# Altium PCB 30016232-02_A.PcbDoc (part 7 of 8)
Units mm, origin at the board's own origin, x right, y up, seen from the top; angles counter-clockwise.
Board outline 210 x 130 mm, 8 copper layers (1-TOP, 2-GND, 3-INTOP, 4-PWR, 5-PWR, 6-INBOT, 7-GND, 8-BOTTOM), stack 1.646 mm thick; 754 components, 649 nets, 2976 pads, 2161 vias.
Unrouted connection lines stored in the file: 22.
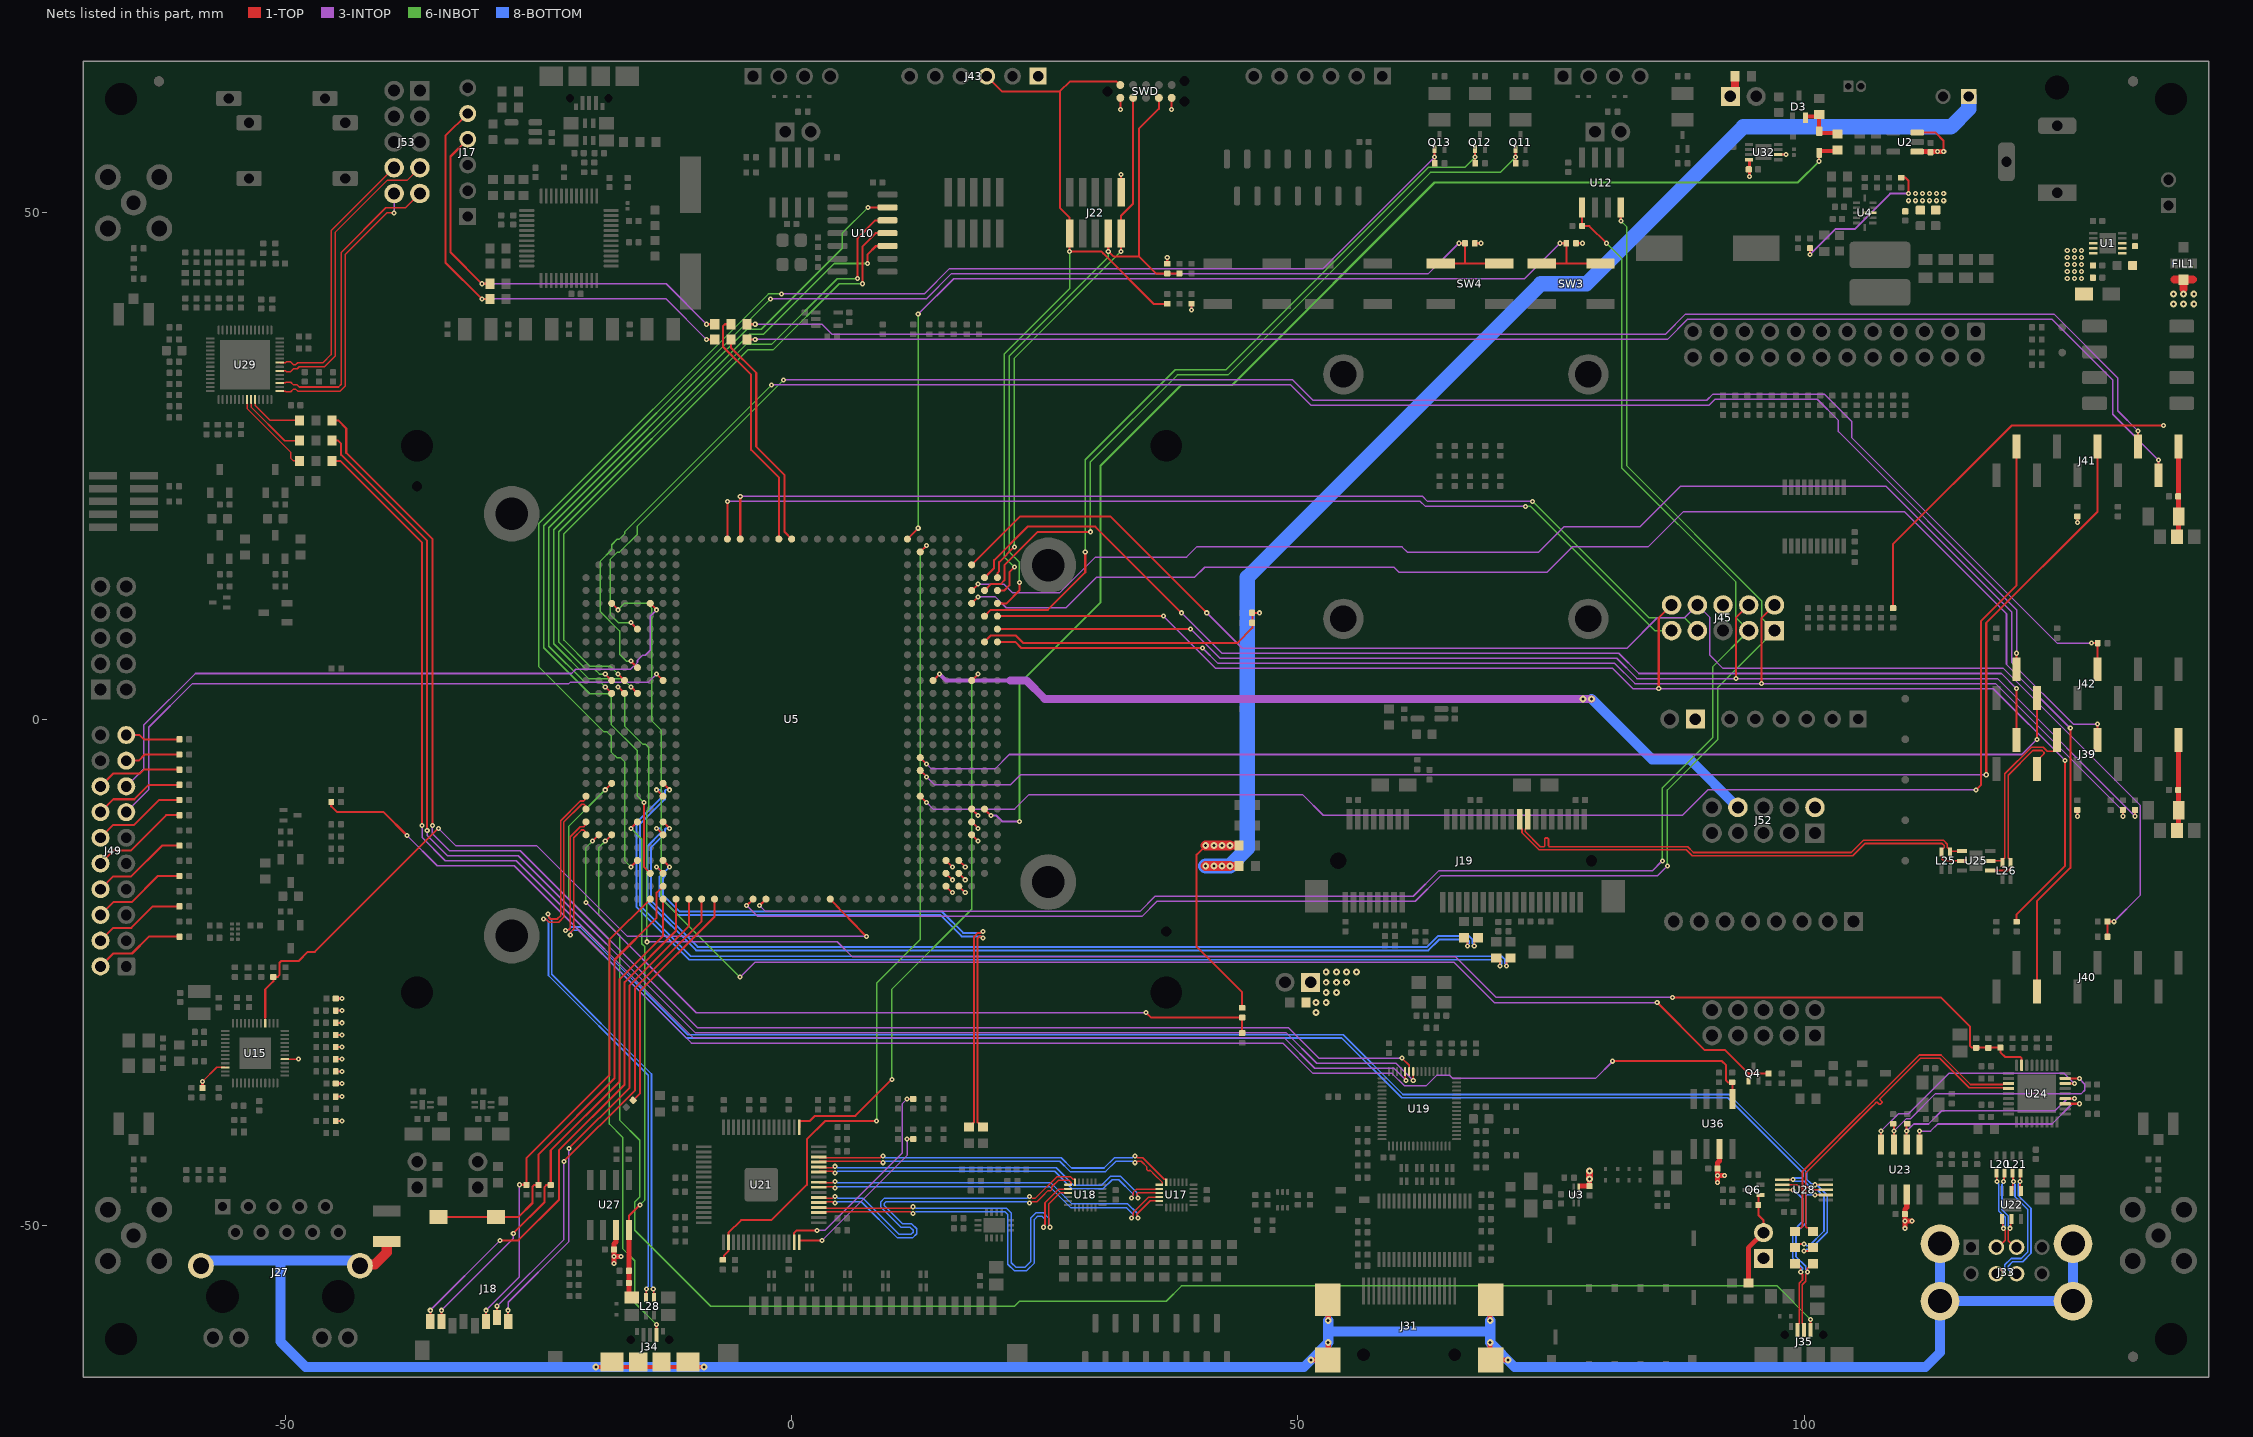
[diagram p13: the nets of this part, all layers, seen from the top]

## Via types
v1: diameter 0.5, hole 0.2, 1-TOP to 8-BOTTOM, 1742 vias
v2: diameter 0.5/0.5/0.5/0.5 (per signal layer), hole 0.2, 1-TOP to 8-BOTTOM, 237 vias
v3: diameter 0.68, hole 0.3, 1-TOP to 8-BOTTOM, 182 vias

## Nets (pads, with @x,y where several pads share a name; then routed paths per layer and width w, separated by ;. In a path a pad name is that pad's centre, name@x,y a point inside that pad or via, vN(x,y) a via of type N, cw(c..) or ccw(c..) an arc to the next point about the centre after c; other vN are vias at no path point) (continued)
SHLD: J27.SHLD1 J27.SHLD2 J31.M1 J31.M2 J31.M3 J31.M4 J33.SH1 J33.SH2 J33.SH3 J33.SH4 J34.6 J34.7 J34.8 J34.9 R180.2 | length 251.6
  1-TOP w0.4: v3(-19.35,-64) -15.15,-64 -12.85,-64 v3(-8.65,-64)
  1-TOP w0.5: v3(51.29,-63.31) J31.M4@52.95,-63.31 53,-63.31 v3(53,-61.6) ; v3(53,-59.4) J31.M2@53,-57.35 ; J31.M3@69,-63.31 v3(69,-61.6) ; v3(69,-59.4) J31.M1@69,-57.35 ; J31.M3@69.05,-63.31 v3(70.76,-63.31)
  1-TOP w1: J27.SHLD2@-42.645,-54 -42.509,-53.864 -41.164,-53.864 -40,-52.7 R180.2@-40,-51.6
  8-BOTTOM w1: J27.SHLD1@-58.355,-53.5 -50.5,-53.5 ; J27.SHLD2@-42.645,-53.5 -50.5,-53.5 ; v3(53,-59.4) 53,-60.5 ; v3(69,-59.4) 69,-60.5 ; J33.SH1@112.939,-57.5 J33.SH1@113.43,-57.5 ; J33.SH2@113.43,-51.82 J33.SH1@113.43,-57.5 ; J33.SH4@126.57,-51.82 J33.SH3@126.57,-57.5 J33.SH1@113.43,-57.5 ; -50.5,-53.5 -50.5,-61.5 -48,-64 -42,-64 -19.4,-64 -19.2,-64 -8.8,-64 v3(-8.65,-64) 50.6,-64 v3(51.29,-63.31) v3(53,-61.6) 53,-60.5 ; 53,-60.5 69,-60.5 ; 69,-60.5 v3(69,-61.6) 71.4,-64 112,-64 113.43,-62.57 J33.SH1@113.43,-57.5
SN65DSI83_CLK_N: U17.23 U21.25 | length 36.6
  1-TOP w0.15: U21.25@2.68,-45.75 2.745,-45.815 3.465,-45.815 3.473,-45.823 3.7,-45.823 4.057,-45.823 4.205,-45.675 v1(4.3,-45.675) ; v1(34.225,-49.3) 34.225,-49.205 34.077,-49.057 34.077,-48.923 35.423,-47.577 36.282,-47.577 U17.23@36.305,-47.6
  8-BOTTOM w0.15: v1(4.3,-45.675) 4.395,-45.675 4.543,-45.823 25.623,-45.823 27.7,-47.9 33.2,-47.9 34.077,-48.777 34.077,-49.057 34.225,-49.205 v1(34.225,-49.3)
SN65DSI83_CLK_P: U17.22 U21.24 | length 36.6
  1-TOP w0.15: U21.24@2.68,-46.25 2.745,-46.185 3.465,-46.185 3.473,-46.177 3.678,-46.177 4.057,-46.177 4.205,-46.325 v1(4.3,-46.325) ; v1(33.575,-49.3) 33.575,-49.205 33.723,-49.057 33.723,-48.776 35.276,-47.223 36.282,-47.223 U17.22@36.305,-47.2
  8-BOTTOM w0.15: v1(4.3,-46.325) 4.395,-46.325 4.543,-46.177 25.476,-46.177 27.553,-48.254 33.053,-48.254 33.723,-48.924 33.723,-49.057 33.575,-49.205 v1(33.575,-49.3)
SN65DSI83_D0_N: U18.21 U21.20 | length 38.2
  1-TOP w0.15: U21.20@2.68,-48.25 2.745,-48.315 3.465,-48.315 3.473,-48.323 11.757,-48.323 ; v1(25.525,-50.2) 25.525,-50.105 25.377,-49.957 25.377,-47.923 26.523,-46.777 27.282,-46.777 U18.21@27.305,-46.8
  8-BOTTOM w0.15: 12.243,-48.323 21.223,-48.323 21.7,-48.8 21.7,-53.7 22.146,-54.146 23.054,-54.146 23.623,-53.577 23.623,-49.276 24.153,-48.746 24.847,-48.746 25.377,-49.276 25.377,-49.957 25.525,-50.105 v1(25.525,-50.2)
  other v1: 12,-48.175
SN65DSI83_D0_P: U18.20 U21.19 | length 38.2
  1-TOP w0.15: U21.19@2.68,-48.75 2.745,-48.685 3.465,-48.685 3.473,-48.677 11.757,-48.677 ; v1(24.875,-50.2) 24.875,-50.105 25.023,-49.957 25.023,-47.776 26.376,-46.423 27.282,-46.423 U18.20@27.305,-46.4
  8-BOTTOM w0.15: 12.243,-48.677 21.076,-48.677 21.346,-48.947 21.346,-53.847 21.999,-54.5 23.201,-54.5 23.977,-53.724 23.977,-49.423 24.3,-49.1 24.7,-49.1 25.023,-49.423 25.023,-49.957 24.875,-50.105 v1(24.875,-50.2)
  other v1: 12,-48.825
SN65DSI83_D1_N: U18.18 U21.22 | length 36.6
  1-TOP w0.15: U21.22@2.68,-47.25 2.745,-47.315 3.465,-47.315 3.473,-47.323 3.825,-47.323 4.057,-47.323 4.205,-47.175 v1(4.3,-47.175) ; v1(23.5,-47.175) 23.595,-47.175 23.743,-47.323 24.076,-47.323 26.176,-45.223 27.573,-45.223 27.798,-45.448 27.975,-45.448 28,-45.472 U18.18@28,-45.755
  8-BOTTOM w0.15: v1(4.3,-47.175) 4.395,-47.175 4.543,-47.323 7.024,-47.323 10.601,-50.9 11.799,-50.9 12,-50.699 12,-50.501 11.699,-50.2 10.8,-50.2 8.8,-48.2 8.8,-47.7 9.177,-47.323 11.3,-47.323 23.257,-47.323 23.405,-47.175 v1(23.5,-47.175)
SN65DSI83_D1_P: U18.19 U21.21 | length 36.6
  1-TOP w0.15: U21.21@2.68,-47.75 2.745,-47.685 3.465,-47.685 3.473,-47.677 3.678,-47.677 4.057,-47.677 4.205,-47.825 v1(4.3,-47.825) ; v1(23.5,-47.825) 23.595,-47.825 23.743,-47.677 24.223,-47.677 24.75,-47.15 25.329,-46.571 25.428,-46.571 25.464,-46.606 25.563,-46.606 25.711,-46.458 25.711,-46.359 25.676,-46.323 25.676,-46.224 25.75,-46.15 26.323,-45.577 27.427,-45.577 27.591,-45.741 27.591,-45.975 27.566,-46 U18.19@27.305,-46
  8-BOTTOM w0.15: v1(4.3,-47.825) 4.395,-47.825 4.543,-47.677 6.877,-47.677 10.454,-51.254 11.946,-51.254 12.354,-50.846 12.354,-50.354 11.846,-49.846 10.947,-49.846 9.154,-48.053 9.154,-47.847 9.324,-47.677 11.3,-47.677 23.257,-47.677 23.405,-47.825 v1(23.5,-47.825)
SN65DSI83_D2_N: U17.21 U21.28 | length 36.6
  1-TOP w0.15: U21.28@2.68,-44.25 2.745,-44.315 3.465,-44.315 3.473,-44.323 3.825,-44.323 4.057,-44.323 4.205,-44.175 v1(4.3,-44.175) ; v1(34.225,-47.3) 34.225,-47.205 34.077,-47.057 34.077,-46.923 34.223,-46.777 36.282,-46.777 U17.21@36.305,-46.8
  8-BOTTOM w0.15: v1(4.3,-44.175) 4.395,-44.175 4.543,-44.323 26.124,-44.323 27.847,-46.046 30.614,-46.046 31.514,-45.146 32.447,-45.146 34.077,-46.776 34.077,-47.057 34.225,-47.205 v1(34.225,-47.3)
SN65DSI83_D2_P: U17.20 U21.27 | length 36.6
  1-TOP w0.15: U21.27@2.68,-44.75 2.745,-44.685 3.465,-44.685 3.473,-44.677 3.678,-44.677 4.057,-44.677 4.205,-44.825 v1(4.3,-44.825) ; v1(33.575,-47.3) 33.575,-47.205 33.723,-47.057 33.723,-46.776 34.076,-46.423 36.282,-46.423 U17.20@36.305,-46.4
  8-BOTTOM w0.15: v1(4.3,-44.825) 4.395,-44.825 4.543,-44.677 25.977,-44.677 27.7,-46.4 30.76,-46.4 31.66,-45.5 32.3,-45.5 33.723,-46.923 33.723,-47.057 33.575,-47.205 v1(33.575,-47.3)
SN65DSI83_D3_N: U17.18 U21.30 | length 36.6
  1-TOP w0.15: U21.30@2.68,-43.25 2.745,-43.315 3.465,-43.315 3.473,-43.323 8.077,-43.323 8.757,-43.323 8.905,-43.175 v1(9,-43.175) ; v1(33.9,-43.175) 33.995,-43.175 34.143,-43.323 34.673,-43.323 36.798,-45.448 36.975,-45.448 37,-45.472 U17.18@37,-45.755
  8-BOTTOM w0.15: v1(9,-43.175) 9.095,-43.175 9.243,-43.323 26.624,-43.323 27.647,-44.346 30.853,-44.346 31.876,-43.323 33.657,-43.323 33.805,-43.175 v1(33.9,-43.175)
SN65DSI83_D3_P: U17.19 U21.29 | length 36.6
  1-TOP w0.15: U21.29@2.68,-43.75 2.745,-43.685 3.465,-43.685 3.473,-43.677 7.93,-43.677 8.757,-43.677 8.905,-43.825 v1(9,-43.825) ; v1(33.9,-43.825) 33.995,-43.825 34.143,-43.677 34.527,-43.677 34.775,-43.925 34.899,-44.049 35.097,-44.247 35.097,-44.346 35.061,-44.381 35.061,-44.48 35.21,-44.629 35.309,-44.629 35.344,-44.593 35.443,-44.593 35.825,-44.975 36.591,-45.741 36.591,-45.975 36.566,-46 U17.19@36.305,-46
  8-BOTTOM w0.15: v1(9,-43.825) 9.095,-43.825 9.243,-43.677 26.477,-43.677 27.5,-44.7 31,-44.7 32.023,-43.677 33.657,-43.677 33.805,-43.825 v1(33.9,-43.825)
SN65DSI83_EN: R243.2 U5.AG28 U21.2 | length 84.6
  1-TOP w0.2: R243.2@-6.7,-53.5 -6.7,-53 -6.25,-52.55 U21.2@-6.25,-51.68 -6.25,-50.75 -5,-49.5 -2,-49.5 1.5,-46 1.5,-41.5 3.3,-39.7 v1(8.4,-39.7) ; U5.AG28@12.7,16.51 v1(13.335,17.145)
  6-INBOT w0.15: v1(8.4,-39.7) 8.4,-26.074 12.7,-21.774 12.7,16.51 v1(13.335,17.145)
SN65DSI83_IRQ: U5.AL18 U21.33 | length 55.9
  1-TOP w0.2: U21.33@0.75,-40.32 0.75,-39.74 0.79,-39.7 1.8,-39.7 2.3,-39.2 6.3,-39.2 v1(9.9,-35.6) ; U5.AL18@17.78,3.81 v1(18.415,4.445)
  6-INBOT w0.15: v1(9.9,-35.6) 9.9,-26.674 17.78,-18.794 17.78,3.81 v1(18.415,4.445)
SN65DSI83_SCL: R297.2 U21.15 | length 21
  1-TOP w0.2: U21.15@0.25,-51.68 0.25,-50.75 0.5,-50.5 v1(2.5,-50.5) ; v1(11.4,-37.52) R297.2@12,-37.52
  3-INTOP w0.15: v1(2.5,-50.5) 3.3,-50.5 10.9,-42.9 10.9,-38.02 v1(11.4,-37.52)
SN65DSI83_SDA: R299.2 U21.16 | length 16.3
  1-TOP w0.2: U21.16@0.8,-51.5 v1(3,-51.5) ; v1(11.4,-41.48) R299.2@12,-41.48
  3-INTOP w0.15: v1(3,-51.5) 11.4,-43.1 v1(11.4,-41.48)
SPI3_CS0: U5.C17 U10.13 | length 67.3
  1-TOP w0.2: v1(-18.415,3.175) U5.C17@-17.78,2.54 ; v1(7.54,50.54) U10.13@9.47,50.54
  6-INBOT w0.15: v1(-18.415,3.175) -18.89,3.65 -20.45,3.65 -24,7.2 -24,18.9 -4.4,38.5 -3,38.5 5,46.5 5,48 v1(7.54,50.54)
SPI3_SCK: U5.E17 U10.10 | length 66.7
  1-TOP w0.2: v1(-15.875,3.175) U5.E17@-15.24,2.54 ; v1(7.5,45) 7.5,45.9 8.33,46.73 U10.10@9.47,46.73
  6-INBOT w0.15: v1(-15.875,3.175) -16.67,3.97 -20.03,3.97 -23.5,7.44 -23.5,18.7 -4.2,38 -2.8,38 4.2,45 v1(7.5,45)
SPI3_SDI: U5.C18 U10.12 | length 65.2
  1-TOP w0.2: v1(-18.415,4.445) U5.C18@-17.78,3.81 ; v1(6.5,43.5) 6.5,43.9 6.5,47.5 8.27,49.27 U10.12@9.47,49.27
  6-INBOT w0.15: v1(-18.415,4.445) -18.992,4.445 -19.467,4.92 -20.32,4.92 -23,7.6 -23,18.5 -4.5,37 -2,37 4.5,43.5 v1(6.5,43.5)
SPI3_SDO: U5.D18 U10.11 | length 64.6
  1-TOP w0.2: v1(-17.145,4.445) U5.D18@-16.51,3.81 ; v1(7,43) 7,46.7 8.3,48 U10.11@9.47,48
  6-INBOT w0.15: v1(-17.145,4.445) -17.92,5.22 -19.92,5.22 -22.5,7.8 -22.5,18.3 -4.3,36.5 -1.8,36.5 4.7,43 v1(7,43)
SPKL_N: J53.8 U29.22 | length 26.7
  1-TOP w0.15: U29.22@-50.57,35.2 -50,35.2 -49.925,35.275 -49.475,35.275 -49.2,35 -49,35 -48.8,35.2 -46.3,35.2 -45.5,36 -45.5,48.23 J53.8@-39.27,54.46
SPKL_P: J53.7 U29.20 | length 29.4
  1-TOP w0.15: U29.20@-50.57,34.4 -50,34.4 -49.925,34.325 -49.475,34.325 -49.2,34.6 -48.834,34.6 -48.634,34.8 -46.134,34.8 -45.1,35.834 -45.1,48.064 -39.964,53.2 -37.99,53.2 J53.7@-36.73,54.46
SPKR_N: J53.10 U29.15 | length 28.4
  1-TOP w0.15: U29.15@-50.57,32.4 -50,32.4 -49.925,32.325 -49.475,32.325 -49.2,32.6 -49,32.6 -48.8,32.4 -44.6,32.4 -44.1,32.9 -44.1,45.9 -40,50 v1(-39.27,50)
  3-INTOP w0.15: v1(-39.27,50) J53.10@-39.27,51.92
SPKR_P: J53.9 U29.17 | length 29.6
  1-TOP w0.15: U29.17@-50.57,33.2 -50,33.2 -49.925,33.275 -49.475,33.275 -49.2,33 -48.834,33 -48.634,32.8 -44.766,32.8 -44.5,33.066 -44.5,46.1 -40.1,50.5 -38.15,50.5 J53.9@-36.73,51.92
SWD_CLK/PWR_IO: J22.4 R1.1 R2.2 SWD.4 U5.AN24 | length 66.8
  1-TOP w0.2: U5.AN24@20.32,11.43 21.23,11.43 22.5,12.7 v1(22.5,13.5) ; J22.4@31.27,47.968 v1(31.27,46.2) 31.77,45.7 34.3,45.7 ; SWD.4@36.27,61.365 36.27,60.27 34.3,58.3 34.3,45.7 ; R2.2@38.3,44.02 R1.1@37.1,44.02 35.98,44.02 34.3,45.7
  6-INBOT w0.15: v1(22.5,13.5) 22.5,15.5 21.5,16.5 21.5,35.86 31.27,45.63 v1(31.27,46.2)
SWD_DIO: J22.2 SWD.2 U5.AN26 | length 52.9
  1-TOP w0.2: U5.AN26@20.32,13.97 20.32,14.42 20.5,14.6 20.5,15.5 v1(22,17) ; v1(32.54,46.2) J22.2@32.54,47.968 32.54,49.74 33.73,50.93 SWD.2@33.73,61.365
  6-INBOT w0.15: v1(22,17) 22,35.66 v1(32.54,46.2)
SYS_RESET: J22.10 J43.3 R5.2 SWD.10 U5.AN25 | length 80.1
  1-TOP w0.2: J43.3@19.27,63.5 20.77,62 26.5,62 ; U5.AN25@20.32,12.7 21,12.7 21.5,13.2 21.5,14.5 v1(22,15) ; SWD.10@32.46,62.635 32.414,62.635 32.049,63 27.5,63 26.5,62 ; R5.2@37.1,41.02 35.743,41.02 30.77,45.993 30.77,46.03 30.6,46.2 v1(27.46,46.2) J22.10@27.46,47.968 27.46,49.54 26.5,50.5 26.5,62
  6-INBOT w0.15: v1(22,15) 21,16 21,36.06 27.46,42.52 v1(27.46,46.2)
TXC_LT8912B: R239.2 U19.60 | length 149.4
  1-TOP w0.15: v1@60.6,-35.7 U19.60@60.6,-34.82
  1-TOP w0.2: R239.2@-45.4,25.5 -44.6,25.5 -36.5,17.4 v1(-36.5,-10.5)
  3-INTOP w0.15: v1(-36.5,-10.5) -36.5,-11.707 -34.213,-13.994 -27.213,-13.994 -9.707,-31.5 48.678,-31.5 51.678,-34.5 59.5,-34.5 v1(60.7,-35.7)
TXC_MAX98089: R238.2 U29.8 | length 8.6
  1-TOP w0.15: U29.8@-53.8,31.57 -53.8,30.669 -49.5,26.369 -49.5,25.8 -49.2,25.5 R238.2@-48.6,25.5
TXD_LT8912B: R236.2 U19.58 | length 151.5
  1-TOP w0.15: v1(61.4,-35.7) U19.58@61.4,-34.82
  1-TOP w0.2: R236.2@-45.4,27.5 -44.8,27.5 -44.5,27.2 -44.5,26.1 -36,17.6 v1(-36,-11)
  3-INTOP w0.15: v1(-36,-11) -36,-11.5 -34.006,-13.494 -27.006,-13.494 -9.5,-31 48.877,-31 51.878,-34 59.7,-34 v1(61.4,-35.7)
TXD_MAX98089: R235.2 U29.9 | length 6.9
  1-TOP w0.15: U29.9@-53.4,31.57 -53.4,30.834 -50.066,27.5 R235.2@-48.6,27.5
TXFS_LT8912B: R241.2 U19.59 | length 151.9
  1-TOP w0.15: v1(60.3,-33.5) 61,-34.2 U19.59@61,-34.82
  1-TOP w0.2: R241.2@-45.4,29.5 -44.8,29.5 -44,28.7 -44,26.3 -35.5,17.8 v1(-35.5,-10.5)
  3-INTOP w0.15: v1(-35.5,-10.5) -35.5,-11.301 -33.801,-13 -26.801,-13 -9.301,-30.5 49.078,-30.5 52.078,-33.5 v1(60.3,-33.5)
TXFS_MAX98089: R240.2 U29.10 | length 5.6
  1-TOP w0.15: U29.10@-53,31.57 -53,31 -51.5,29.5 R240.2@-48.6,29.5
UART3_CTS_B: J45.9 U5.M29 | length 102.3
  1-TOP w0.2: U5.M29@-6.35,17.78 v1(-6.35,21.5)
  3-INTOP w0.15: v1(-6.35,21.5) 62.1,21.5 62.6,21 v1(72.5,21)
  6-INBOT w0.15: v1(72.5,21) 73,21 85.27,8.73 J45.9@86.92,8.73
UART3_RTS_B: J45.7 U5.N29 | length 104.3
  1-TOP w0.2: U5.N29@-5.08,17.78 v1(-5.08,22)
  3-INTOP w0.15: v1(-5.08,22) 62.3,22 62.8,21.5 v1(73.2,21.5)
  6-INBOT w0.15: v1(73.2,21.5) 84.7,10 88.19,10 J45.7@89.46,8.73
UART3_RX: J45.3 R177.1 U5.R1 U12.1 | length 167.7
  1-TOP w0.2: v1(-3.175,-18.415) U5.R1@-2.54,-17.78 ; R177.1@78.08,48.7 R177.1@78.085,48.7 ; U12.1@78.085,50.53 R177.1@78.085,48.7 ; v1(80.5,47) 78.8,48.7 R177.1@78.085,48.7
  3-INTOP w0.15: v1(-3.175,-18.415) -2.59,-19 34.4,-19 35.9,-17.5 61.4,-17.5 63.9,-15 85,-15 v1(86,-14)
  6-INBOT w0.15: v1(80.5,47) 82,45.5 82,24.8 93.27,13.53 93.27,10 J45.3@94.54,8.73 91,5.19 91,-1.8 86,-6.8 v1(86,-14)
UART3_TX: J45.1 U5.P1 U12.4 | length 170.1
  1-TOP w0.2: v1(-4.445,-18.415) U5.P1@-3.81,-17.78 ; v1@81.895,49.2 U12.4@81.895,50.53
  3-INTOP w0.15: v1(-4.445,-18.415) -3.36,-19.5 34.6,-19.5 36.1,-18 61.6,-18 64.1,-15.5 85.5,-15.5 v1(86.5,-14.5)
  6-INBOT w0.15: v1(81.9,49.2) 82.5,48.6 82.5,25 95.81,11.69 95.81,10 J45.1@97.08,8.73 91.5,3.15 91.5,-2 86.5,-7 v1(86.5,-14.5)
UART4_RX: R153.1 R154.1 U5.U29 | length 22.2
  1-TOP w0.2: R153.1@-6,37.5 -6,36.7 -3.5,34.2 -3.5,26.9 -0.7,24.1 -0.7,18.48 U5.U29@0,17.78
UART4_TX: R151.1 R152.1 U5.T29 | length 24.1
  1-TOP w0.2: R151.1@-6.1,39 -6.6,39 -6.8,38.8 -6.8,36.8 -4,34 -4,26.6 -1.27,23.87 U5.T29@-1.27,17.78
UART_M7_RX: J17.5 R146.2 R153.2 | length 46.2
  1-TOP w0.2: J17.5@-32,59.81 -34.2,57.61 -34.2,45.1 v1(-30.6,41.5) R146.2@-29.8,41.5 ; v1(-8.4,37.5) R153.2@-7.6,37.5
  3-INTOP w0.15: v1(-30.6,41.5) -12.4,41.5 v1(-8.4,37.5)
UART_M7_TX: J17.4 R147.2 R151.2 | length 41.7
  1-TOP w0.2: J17.4@-32,57.27 -33.7,55.57 -33.7,46.1 v1(-30.6,43) R147.2@-29.8,43 ; v1(-8.4,39) R151.2@-7.6,39
  3-INTOP w0.15: v1(-30.6,43) -12.4,43 v1(-8.4,39)
USB_HUB_N: R267.2 U24.30 U28.7 | length 35
  1-TOP w0.168: U28.7@97.84,-46 99.3,-46 99.55,-46.25 99.841,-46.25 ; R267.2@99.1,-50.6 99.466,-50.234 99.743,-50.234 ; U24.30@120.2,-36 120.134,-36.066 119.661,-36.066 119.636,-36.091 116.441,-36.091 113.532,-33.182 111.368,-33.182 99.841,-44.709 99.841,-49.676 99.841,-50.136 ; 99.743,-50.234 99.841,-50.136 ; 99.743,-50.234 99.841,-50.136
USB_HUB_P: R265.2 U24.31 U28.3 | length 35
  1-TOP w0.168: R265.2@100.9,-50.6 100.534,-50.234 100.257,-50.234 100.159,-50.136 100.159,-49.544 100.159,-46.25 ; U28.3@102.16,-46.5 100.7,-46.5 100.45,-46.25 100.159,-46.25 ; U24.31@120.2,-36.5 120.134,-36.434 119.661,-36.434 119.636,-36.409 116.309,-36.409 113.4,-33.5 111.5,-33.5 108,-37 107.503,-37.497 107.503,-37.602 107.695,-37.794 107.695,-37.898 107.539,-38.054 107.435,-38.054 107.242,-37.862 107.138,-37.862 106.93,-38.07 106.8,-38.2 100.159,-44.841 100.159,-46.25
USB_HUB_RESET_N: C127.2 R250.1 R252.2 U5.D17 U24.26 | length 170.2
  1-TOP w0.2: v1(-17.145,3.175) U5.D17@-16.51,2.54 ; v1(87,-27.5) 113.5,-27.5 116.4,-30.4 116.4,-32.3 116.56,-32.46 C127.2@119.4,-32.46 119.4,-32.9 119.9,-33.4 121.4,-33.4 121.5,-33.5 U24.26@121.5,-34.2
  3-INTOP w0.15: v1(-14.3,-22) 4.5,-22 6,-23.5 65.607,-23.5 69.607,-27.5 v1(87,-27.5)
  6-INBOT w0.15: v1(-17.145,3.175) -16.51,2.54 -16.51,-0.672 -14.682,-2.5 -14.425,-2.5 -14.125,-2.8 -14.125,-8.9 -14.3,-9.075 v1(-14.3,-22)
USB_OTG1_ID: J35.4 U5.C6 | length 164
  1-TOP w0.2: v1(-18.415,-12.065) U5.C6@-17.78,-11.43 ; J35.4@100.65,-60.35 v1(100.65,-59.3)
  6-INBOT w0.15: v1(-18.415,-12.065) -19.05,-12.7 -19.05,-19.35 -17,-21.4 -17,-39.6 -15,-41.6 -15,-47.2 -15.5,-47.7 -15.5,-50.5 -8,-58 22,-58 22.5,-57.5 37,-57.5 38.5,-56 97.35,-56 v1(100.65,-59.3)
USB_OTG1_N: R266.1 R267.1 U5.A6 U28.6 | length 157.1
  1-TOP w0.168: v1(-21.87,-21.33) -21.807,-21.266 -21.807,-21.032 -21.541,-20.766 -21.541,-11.741 -20.754,-10.954 -20.556,-10.954 -20.422,-11.088 -20.422,-11.328 U5.A6@-20.32,-11.43 ; U28.6@97.84,-45.5 v1(98.9,-45.5)
  1-TOP w0.2: R266.1@98.9,-51.875 v1(100,-51.875)
  8-BOTTOM w0.168: v1(-21.87,-21.33) -21.807,-21.266 -21.807,-21.032 -21.634,-20.859 -21.041,-20.859 -10.4,-31.5 54.35,-31.5 60.25,-37.4 92.45,-37.4 99.927,-44.877 99.927,-45.173 99.759,-45.341 99.059,-45.341 v1(98.9,-45.5) 99.059,-45.659 100.009,-45.659 100.85,-46.5 101.3,-46.5 101.966,-47.166 101.966,-50.575 100.5,-52.041 100.256,-52.041 100.09,-51.875 v1(100,-51.875)
USB_OTG1_P: R263.1 R265.1 U5.A7 U28.4 | length 156.9
  1-TOP w0.168: v1(-22.33,-20.87) -22.266,-20.807 -22.032,-20.807 -21.859,-20.634 -21.859,-11.609 -20.886,-10.636 -20.556,-10.636 -20.422,-10.502 -20.422,-10.262 U5.A7@-20.32,-10.16 ; v1(101.1,-46) U28.4@102.16,-46
  1-TOP w0.2: v1(100,-52.525) R265.1@101.1,-52.525
  8-BOTTOM w0.168: v1(-22.33,-20.87) -22.266,-20.807 -22.032,-20.807 -21.766,-20.541 -20.909,-20.541 -10.268,-31.182 54.482,-31.182 60.382,-37.082 92.582,-37.082 100.245,-44.745 100.245,-45.445 100.7,-45.9 101,-45.9 v1(101.1,-46) 101.25,-46 102.284,-47.034 102.284,-50.707 100.632,-52.359 100.256,-52.359 100.09,-52.525 v1(100,-52.525)
USB_OTG1_POWER: R350.2 R353.1 U36.1 | length 154.9
  1-TOP w0.2: R353.1@-45.48,-8.2 -45.48,-8.62 -44.9,-9.2 -40.3,-9.2 v1(-38,-11.5) ; v1(81.1,-33.8) 91.9,-33.8 92.3,-34.2 92.3,-35.7 92.48,-35.88 R350.2@92.9,-35.88 ; U36.1@92.915,-37.53 R350.2@92.915,-35.88
  3-INTOP w0.15: v1(-38,-11.5) -35,-14.5 -27.407,-14.5 -9.907,-32 48.5,-32 51.5,-35 59.3,-35 60.5,-36.2 62.7,-36.2 63.7,-35.2 65,-35.2 65.3,-35.5 79.4,-35.5 v1(81.1,-33.8)
USB_OTG1_VBUS: R342.1 R354.1 U5.B6 | length 78.3
  1-TOP w0.2: v1(-19.685,-12.065) U5.B6@-19.05,-11.43 ; v1(35,-29) 35.5,-29.5 44.48,-29.5 R354.1@44.5,-29.48 R342.1@44.5,-31
  3-INTOP w0.15: v1(-20.32,-18.1) -9.42,-29 v1(35,-29)
  6-INBOT w0.15: v1(-20.32,-18.1) -20.32,-12.7 v1(-19.685,-12.065)
USB_OTG2_ID: J34.4 U5.C10 | length 59.8
  1-TOP w0.2: v1(-18.415,-6.985) U5.C10@-17.78,-6.35 ; J34.4@-13.35,-60.85 v1(-13.35,-59.8)
  6-INBOT w0.15: v1(-18.415,-6.985) -22,-10.57 -22,-17.8 -18,-21.8 -18,-40 -16.7,-41.3 -16.7,-52.3 -15.5,-53.5 -15.5,-57.65 v1(-13.35,-59.8)
USB_OTG2_N: L28.1 U5.A8 | length 57
  1-TOP w0.168: v1(-24.53,-19.73) -24.466,-19.793 -24.232,-19.793 -23.966,-20.059 -23.009,-20.059 -22.5,-19.55 -22.5,-10.17 -20.744,-8.414 -20.556,-8.414 -20.422,-8.548 -20.422,-8.788 U5.A8@-20.32,-8.89 ; L28.1@-14.4,-57.15 -14.362,-57.112 -14.362,-56.337 v1(-14.325,-56.3)
  8-BOTTOM w0.168: v1(-24.53,-19.73) -24.466,-19.793 -24.232,-19.793 -24.018,-20.007 -24.018,-25.332 -14.159,-35.191 -14.159,-56.044 -14.325,-56.21 v1(-14.325,-56.3)
USB_OTG2_P: L28.4 U5.A9 | length 57
  1-TOP w0.168: v1(-24.07,-19.27) -24.007,-19.334 -24.007,-19.568 -23.834,-19.741 -23.141,-19.741 -22.818,-19.418 -22.818,-10.038 -20.876,-8.096 -20.556,-8.096 -20.422,-7.962 -20.422,-7.722 U5.A9@-20.32,-7.62 ; v1(-13.675,-56.3) -13.638,-56.337 -13.638,-57.112 L28.4@-13.6,-57.15
  8-BOTTOM w0.168: v1(-24.07,-19.27) -24.007,-19.334 -24.007,-19.568 -23.7,-19.875 -23.7,-25.2 -13.841,-35.059 -13.841,-56.044 -13.675,-56.21 v1(-13.675,-56.3)
USB_OTG2_VBUS: C142.2 C143.2 L27.2 U5.E7 U27.8 | length 48.2
  1-TOP w0.2: U27.8@-16.085,-50.47 -16.085,-49.085 v1(-15,-48) ; v1(-15.875,-10.795) U5.E7@-15.24,-10.16
  1-TOP w0.5: L27.2@-16.085,-56.865 U27.8@-16.085,-50.47
  6-INBOT w0.15: v1(-15.875,-10.795) -14.8,-11.87 -14.8,-22.2 -14.5,-22.5 -14.5,-47.5 v1(-15,-48)
USB_PCIe_D_N: J19.36 L25.3 U25.2 | length 48.2
  1-TOP w0.168: J19.36@71.9,-9.9 71.9,-10.625 72.141,-10.866 72.141,-11.241 73.818,-12.918 79,-12.918 88.368,-12.918 88.95,-13.5 104.8,-13.5 106,-12.3 113.65,-12.3 113.841,-12.491 113.841,-12.686 113.743,-12.784 113.716,-12.784 113.6,-12.9 L25.3@113.6,-13.15 113.6,-13.8 113.8,-14 U25.2@115.6,-14
USB_PCIe_D_P: J19.38 L25.2 U25.1 | length 48.2
  1-TOP w0.168: J19.38@72.7,-9.9 72.7,-10.625 72.459,-10.866 72.459,-11.109 73.95,-12.6 74.2,-12.6 74.31,-12.6 74.384,-12.526 74.384,-11.821 74.458,-11.747 74.678,-11.747 74.752,-11.821 74.752,-12.526 74.826,-12.6 76.4,-12.6 88.5,-12.6 89.082,-13.182 104.668,-13.182 105.868,-11.982 113.782,-11.982 114.159,-12.359 114.159,-12.686 114.257,-12.784 114.284,-12.784 114.4,-12.9 L25.2@114.4,-13.05 ; L25.2@114.4,-13.15 L25.2@114.4,-13.05 ; U25.1@115.6,-13.05 L25.2@114.4,-13.05
USB_PWR: Q4.G R260.2 U5.C24 | length 152.3
  1-TOP w0.2: U5.C24@-17.78,11.43 v1(-17.145,10.795) ; v1(85.5,-28) 90.2,-32.7 92.2,-32.7 94.5,-35 ; Q4.G@94.5,-35.69 94.5,-35 ; R260.2@96.6,-35 94.5,-35
  3-INTOP w0.15: v1(-5.1,-25.5) -3.6,-24 65.4,-24 69.4,-28 v1(85.5,-28)
  6-INBOT w0.15: v1(-17.145,10.795) -16.51,11.43 -14.33,11.43 -13.81,10.91 -13.81,-0.19 -12.86,-1.14 -12.86,-17.74 v1(-5.1,-25.5)
USB_RECOVERY_N: J35.2 R266.2 U28.8 | length 17.2
  1-TOP w0.168: U28.8@97.84,-46.5 v1(98.9,-46.5) ; J35.2@99.35,-60.35 99.35,-59.85 99.516,-59.684 99.516,-57.584 99.516,-55.734 99.841,-55.409 99.841,-54.856 99.675,-54.69 v1(99.675,-54.6) 99.675,-54.275 R266.2@99.4,-54
  8-BOTTOM w0.168: v1(98.9,-46.5) 99,-46.5 99.841,-47.341 99.841,-49.659 98.882,-50.618 98.882,-53.232 99.841,-54.191 99.841,-54.344 99.675,-54.51 v1(99.675,-54.6)
USB_RECOVERY_P: J35.3 R263.2 U28.2 | length 17.1
  1-TOP w0.168: J35.3@100,-60.35 100,-59.85 99.834,-59.684 99.834,-57.452 99.834,-55.866 100.159,-55.541 100.159,-54.856 100.325,-54.69 v1(100.325,-54.6) 100.325,-54.275 R263.2@100.6,-54 ; v1(101.1,-47) U28.2@102.16,-47
  8-BOTTOM w0.168: v1(100.325,-54.6) 100.325,-54.51 100.159,-54.344 100.159,-54.059 99.2,-53.1 99.2,-50.75 100.159,-49.791 100.159,-47.1 100.259,-47 v1(101.1,-47)
USB_RECOVERY_VBUS: J36.2 Q6.G R264.2 R355.1 | length 9
  1-TOP w0.2: Q6.G@95.5,-47 95.5,-49 96,-49.5 J36.2@96,-50.73
  1-TOP w0.5: 94.5,-55.2 94.5,-52.23 J36.2@96,-50.73
USBH1_D_N: J33.A2 L20.2 U22.1 | length 9.2
  1-TOP w0.168: J33.A2@119,-52.17 119.168,-52.17 119.866,-51.472 119.866,-50.556 119.7,-50.39 v1(119.7,-50.3) 119.636,-50.236 119.636,-49.486 U22.1@119.55,-49.4 ; L20.2@119,-44.85 119.037,-44.887 119.037,-45.662 v1(119.075,-45.7)
  8-BOTTOM w0.168: v1(119.075,-45.7) 119.075,-45.79 119.241,-45.956 119.241,-48.591 119.866,-49.216 119.866,-50.044 119.7,-50.21 v1(119.7,-50.3)
USBH1_D_P: J33.A3 L20.3 U22.2 | length 9.2
  1-TOP w0.168: v1(119.725,-45.7) 119.762,-45.662 119.762,-44.887 L20.3@119.8,-44.85 ; U22.2@120.5,-49.4 120.414,-49.486 120.414,-50.236 v1(120.35,-50.3) 120.35,-50.39 120.184,-50.556 120.184,-51.522 120.832,-52.17 J33.A3@121,-52.17
  8-BOTTOM w0.168: v1(119.725,-45.7) 119.725,-45.79 119.559,-45.956 119.559,-48.459 120.184,-49.084 120.184,-50.044 120.35,-50.21 v1(120.35,-50.3)
USBH1_OC_N: R247.1 U23.2 U24.13 | length 20.8
  1-TOP w0.2: U23.2@110.145,-42.03 R247.1@110.145,-40 ; U24.13@125.8,-37.5 v1(126.7,-37.5)
  3-INTOP w0.15: v1(110.145,-40.7) 110.845,-40 112.3,-40 113.6,-38.7 124.8,-38.7 126,-37.5 v1(126.7,-37.5)
USBH1_PWR_EN: U23.1 U24.12 | length 19.6
  1-TOP w0.2: U23.1@111.415,-42.03 v1(111.415,-40.7) ; U24.12@125.8,-38 v1(127.2,-38)
  3-INTOP w0.15: v1(111.415,-40.7) 112.5,-40.7 113.2,-40 124.5,-40 126.5,-38 v1(127.2,-38)
USBH2_D_N: J33.B2 L21.2 U22.5 | length 13.6
  1-TOP w0.168: U22.5@120.5,-46.6 120.611,-46.489 120.611,-45.764 v1(120.675,-45.7) 120.637,-45.662 120.637,-44.887 L21.2@120.6,-44.85
  8-BOTTOM w0.168: J33.B2@119,-54.79 119.367,-54.79 119.722,-54.435 119.743,-54.435 119.841,-54.336 119.841,-53.909 120.468,-53.282 121.468,-53.282 122.1,-52.65 122.1,-48.45 120.841,-47.191 120.841,-45.956 120.675,-45.79 v1(120.675,-45.7)
USBH2_D_P: J33.B3 L21.3 U22.4 | length 13.6
  1-TOP w0.168: v1@121.275,-45.7 121.339,-45.764 121.339,-46.489 U22.4@121.45,-46.6 ; v1@121.362,-45.662 121.362,-44.887 L21.3@121.4,-44.85
  8-BOTTOM w0.168: J33.B3@121,-54.79 120.633,-54.79 120.278,-54.435 120.257,-54.435 120.159,-54.336 120.159,-54.041 120.6,-53.6 121.6,-53.6 122.418,-52.782 122.418,-48.318 121.159,-47.059 121.159,-45.956 121.325,-45.79 v1(121.325,-45.7)
USBH2_OC_N: R248.1 U23.3 U24.17 | length 25.4
  1-TOP w0.2: U23.3@108.875,-42.03 R248.1@108.875,-40 ; U24.17@125.8,-35.5 v1(127.2,-35.5)
  3-INTOP w0.15: v1(108.875,-40.7) 110.075,-39.5 110.5,-39.5 113,-37 127.4,-37 127.738,-36.662 127.738,-36.063 127.2,-35.525 v1(127.2,-35.5)
USBH2_PWR_EN: U23.4 U24.16 | length 24.1
  1-TOP w0.2: U23.4@107.605,-42.03 v1(107.605,-40.7) ; U24.16@125.8,-36 v1(126.7,-36)
  3-INTOP w0.15: v1(107.605,-40.7) 109.305,-39 110.3,-39 114.3,-35 125.7,-35 v1(126.7,-36)
USDHC2_CD_B: J18.9 J18.10 R158.2 U5.G2 | length 46.3
  1-TOP w0.2: J18.10@-35.2,-48.9 J18.10@-34.9,-49.2 -30.1,-49.2 ; J18.9@-29.2,-49.2 -27,-49.2 -25.6,-47.8 -25.6,-46.2 -25.42,-46.02 R158.2@-25,-46.02 -25,-43 -17.5,-35.5 -17.5,-23.8 -13.335,-19.635 -13.335,-17.145 U5.G2@-12.7,-16.51
USDHC2_CLK: R161.1 U5.L1 | length 23.2
  1-TOP w0.2: R161.1@-15.661,-37.661 -15,-37 -15,-26.9 -7.62,-19.52 U5.L1@-7.62,-17.78
USDHC2_CMD: J18.3 R157.1 U5.F1 | length 48.9
  1-TOP w0.2: J18.3@-30.2,-59.5 v1(-30.2,-58.4) ; v1(-26.9,-46) R157.1@-26.2,-46 ; R157.1@-26.2,-46.02 R157.1@-26.2,-46 ; U5.F1@-13.97,-17.78 -18,-21.81 -18,-35.2 -26.2,-43.4 R157.1@-26.2,-46
  3-INTOP w0.15: v1(-30.2,-58.4) -26.9,-55.1 v1(-26.9,-46)
USDHC2_DATA0: J18.7 R159.1 U5.G1 | length 51
  1-TOP w0.2: J18.7@-34.6,-59.5 v1(-34.6,-58.4) ; v1@-27.496,-50.804 -24.4,-47.707 -24.4,-46.2 -24.22,-46.02 R159.1@-23.8,-46.02 -23.8,-42.6 -17,-35.8 -17,-25.7 -12.7,-21.4 U5.G1@-12.7,-17.78
  3-INTOP w0.15: v1(-34.6,-58.4) -27.5,-51.3 v1(-27.5,-50.8)
USDHC2_DATA1: J18.8 U5.H1 | length 52.8
  1-TOP w0.2: J18.8@-35.7,-59.5 v1(-35.7,-58.4) ; v1(-28.8,-51.5) -26.993,-51.5 -23,-47.507 -23,-42.6 -16.5,-36.1 -16.5,-25.993 -11.43,-20.923 U5.H1@-11.43,-17.78
  3-INTOP w0.15: v1(-35.7,-58.4) v1(-28.8,-51.5)
USDHC2_DATA2: J18.1 U5.J1 | length 49.1
  1-TOP w0.2: J18.1@-28,-59.5 v1(-28,-58.4) ; v1(-22,-42.4) -16,-36.4 -16,-26.3 -10.16,-20.46 U5.J1@-10.16,-17.78
  3-INTOP w0.15: v1(-28,-58.4) -28,-57.6 -22,-51.6 v1(-22,-42.4)
USDHC2_DATA3: J18.2 U5.K1 | length 49.7
  1-TOP w0.2: J18.2@-29.1,-59.1 v1(-29.1,-58) ; v1(-22.5,-43.7) -15.5,-36.7 -15.5,-26.6 -8.89,-19.99 U5.K1@-8.89,-17.78
  3-INTOP w0.15: v1(-29.1,-58) -22.5,-51.4 v1(-22.5,-43.7)
USER_BUTTON1: R320.1 SW3.3 SW3.4 U5.AF29 | length 97.4
  1-TOP w0.2: U5.AF29@11.43,17.78 v1(12.5,18.85) ; SW3.4@74.1,45 76.52,45 ; v1(75.9,47) R320.1@76.52,47 76.52,45 ; SW3.3@79.9,45 76.52,45
  3-INTOP w0.15: v1(12.5,40) 16,43.5 72.4,43.5 v1(75.9,47)
  6-INBOT w0.15: v1(12.5,18.85) v1(12.5,40)
USER_BUTTON2: R321.1 SW4.3 SW4.4 U5.F3 | length 150.1
  1-TOP w0.2: v1(-14.605,-8.255) -14.605,-14.605 U5.F3@-13.97,-15.24 ; SW4.4@64.1,45 66.52,45 ; v1(65.9,47) R321.1@66.52,47 66.52,45 ; SW4.3@69.9,45 67.48,45 66.52,45
  3-INTOP w0.15: v1(-2.1,41.5) 13.3,41.5 15.8,44 62.9,44 v1(65.9,47)
  6-INBOT w0.15: v1(-14.605,-8.255) -15.24,-7.62 -15.24,-3.138 -17.8,-0.578 -17.8,2.1 -18.2,2.5 -19.947,2.5 -24.5,7.053 -24.5,19.1 v1(-2.1,41.5)
USER_LED1: Q11.G R317.1 U5.AM25 | length 76.5
  1-TOP w0.2: U5.AM25@19.05,12.7 19.685,13.335 20.635,13.335 21,13.7 21,15.2 24.3,18.5 v1(29.5,18.5) ; R317.1@71.5,54.9 Q11.G@71.5,56.31
  6-INBOT w0.15: v1(29.5,18.5) 29.5,25.4 38.1,34 43.1,34 63.1,54 70,54 v1(71.5,55.5)
USER_LED2: Q12.G R318.1 U5.AM23 | length 75.1
  1-TOP w0.2: U5.AM23@19.05,10.16 19.685,10.795 25.295,10.795 29,14.5 v1(29,16.5) ; R318.1@67.5,54.9 Q12.G@67.5,56.31
  6-INBOT w0.15: v1(29,16.5) 29,25.607 37.893,34.5 42.9,34.5 62.9,54.5 66.5,54.5 v1(67.5,55.5)
USER_LED3: Q13.G R319.1 U5.E4 | length 144
  1-TOP w0.2: v1(-15.875,-14.605) U5.E4@-15.24,-13.97 ; R319.1@63.5,54.9 Q13.G@63.5,56.31
  3-INTOP w0.15: v1(-1,42) 13.1,42 15.6,44.5 52.5,44.5 v1(63.5,55.5) v1@63.5,55.6
  6-INBOT w0.15: v1(-15.875,-14.605) -16.51,-13.97 -16.51,-4.2 -16.9,-3.81 -17.29,-3.81 -17.8,-3.3 -17.8,-1.7 -18.23,-1.27 -18.53,-1.27 -25,5.2 -25,19.3 -2.3,42 v1(-1,42)
VCC_LICELL: D2.A R349.1 U5.AM8 | length 128.3
  1-TOP w0.2: U5.AM8@19.05,-8.89 v1(19.685,-9.525) ; v1(101.5,55.1) D2.A@101.5,55.93
  1-TOP w0.4: D2.A@101.7,56.1 R349.1@103.3,56.1
  3-INTOP w0.2: v1(19.685,-9.525) 20.225,-9.525 20.8,-10.1 v1(22.5,-10.1)
  6-INBOT w0.2: v1(22.5,-10.1) 22.5,3.499 30.5,11.499 30.5,25 38.5,33 43.5,33 63.5,53 88.6,53 99.4,53 v1(101.5,55.1)
VCC_MCA: C185.2 J3.1 J9.1 J22.1 J43.1 J45.6 J52.2 R1.2 R3.2 R13.2 R320.2 R321.2 R341.2 R348.2 SWD.1 SWD.5 U5.AM21 U32.2 U32.8 | length 40.8
  1-TOP w0.2: U5.AM21@19.05,7.62 19.685,8.255 22.145,8.255 22.9,7.5 44,7.5 45.5,9 R348.2@45.5,10.5 ; v1(32.46,60.2) SWD.1@32.46,61.365 ; J22.1@32.54,52.032 v1(32.54,53.8) ; R1.2@37.1,44.98 v1(37.1,45.6) ; v1(37.54,60.2) SWD.5@37.54,61.365 ; v1(39.5,40.4) R3.2@39.5,41.02 ; R348.2@45.48,10.5 v1(46.22,10.5) ; R321.2@67.48,47 v1(68.1,47) ; R320.2@77.48,47 v1(78.1,47) ; U32.2@97.45,55.75 v1(98.215,55.75)
  1-TOP w0.3: v1(94.6,53.6) U32.8@94.6,55.2
  1-TOP w0.8: J3.1@93.2,61.5 R13.2@93.2,63.5
VCC_RTC: D2.K D3.2 R12.2 R349.2 | length 4.4
  1-TOP w0.4: D3.2@100.15,59.5 101.5,59.5 D2.K@101.5,58.1 ; D2.K@101.6,57.9 R349.2@103.3,57.9
VDDA_1V8: J52.8 U5.AH18 | length 85.2
  1-TOP w0.2: U5.AH18@13.97,3.81 v1(14.605,4.445)
  3-INTOP w0.4: v1(14.605,4.445) 15.24,3.81 21.59,3.81
  3-INTOP w0.8: 21.59,3.81 23.19,3.81 25,2 v3(78.175,2) v3(79,2)
  8-BOTTOM w1: v3(79,2) 85,-4 88.73,-4 J52.8@93.46,-8.73
VDDH1: C74.2 R188.2 R193.2 U15.10 | length 4.7
  1-TOP w0.15: v1(-58.2,-35.8) -56.8,-34.4 U15.10@-55.95,-34.4
  1-TOP w0.2: R188.2@-45.04,-39.7 v1(-44.4,-39.7) ; R193.2@-45.04,-37.3 v1(-44.4,-37.3)
  1-TOP w0.3: C74.2@-58.2,-36.44 v1(-58.2,-35.8)
VDDIO1: C72.2 C73.2 R186.2 R187.2 R189.2 R190.2 R191.2 R192.2 U15.29 | length 6.5
  1-TOP w0.15: U15.29@-50.05,-33.6 v1(-48.7,-33.6)
  1-TOP w0.2: R192.2@-45.04,-34.8 v1(-44.4,-34.8) ; R190.2@-45.04,-33.6 v1(-44.4,-33.6) ; R187.2@-45.04,-32.4 v1(-44.4,-32.4) ; R186.2@-45.04,-31.2 v1(-44.4,-31.2) ; R189.2@-45.04,-30 v1(-44.4,-30) ; R191.2@-45.04,-28.8 v1(-44.4,-28.8)
  1-TOP w0.3: C72.2@-45.04,-36 v1(-44.4,-36) ; C73.2@-45.04,-27.6 v1(-44.4,-27.6)
VIN: C1.2 C7.2 FIL1.3 J36.1 R7.2 R9.2 U1.1 U1.2 U1.3 U2.1 U2.3 | length 47.2
  1-TOP w0.2: R9.2@108.8,10.96 108.8,17.3 120.5,29 122.4,29 v1(135.5,29) ; U2.3@111.18,57.95 112.95,57.95 113.8,57.1 v1(113.8,56.05)
  1-TOP w0.5: U2.1@111.18,56.05 v1(113.2,56.05) v1(113.8,56.05)
  1-TOP w0.8: 136.6,43.4 FIL1.3@137.5,43.4 ; 137.5,42.5 FIL1.3@137.5,43.4 ; 138.4,43.4 FIL1.3@137.5,43.4
  other v3: 136.5,41 137.5,41 138.5,41 136.5,42 137.5,42 138.5,42
VIN_PROT: C2.1 C3.2 C4.2 C10.2 C11.2 C12.2 C13.2 C126.1 C141.2 C194.2 J6.1 R21.2 R23.2 R28.1 R305.1 R310.1 U1.8 U1.9 U1.10 U3.3 U4.3 U4.14 U23.7 U27.7 U36.7 | length 30.9
  1-TOP w0.2: v1(100.6,45.9) R21.2@100.6,46.52 ; R23.2@109.6,53.48 110.02,53.48 110.3,53.2 v1(110.3,51.9) ; v1(127,-9.6) R305.1@127,-8.98 ; v1(127,19.4) R310.1@127,20.02
  1-TOP w0.5: v1(-17.54,-53.8) v1(-17.54,-53.1) ; U27.7@-17.355,-50.47 -17.355,-51.655 -17.54,-51.84 C141.2@-17.54,-52.4 v1(-17.54,-53.1) ; v1(-16.84,-53.1) v1(-17.54,-53.1) ; 77.9,-46.14 C10.2@78.8,-46.14 v3(78.8,-45.44) ; v1(91.46,-45.8) v1(91.46,-45.1) ; U36.7@91.645,-42.47 91.645,-43.655 91.46,-43.84 C194.2@91.46,-44.4 v1(91.46,-45.1) ; v1(92.16,-45.1) v1(91.46,-45.1) ; v1(109.96,-50.3) v1(109.96,-49.6) ; U23.7@110.145,-46.97 110.145,-48.255 109.96,-48.44 C126.1@109.96,-48.9 v1(109.96,-49.6) ; v1(110.66,-49.6) v1(109.96,-49.6)
  1-TOP w0.7: v3(78.8,-45.44) v3(78.8,-44.64)
  3-INTOP w0.2: v1(100.6,45.9) 103.1,48.4 105,48.4 108.5,51.9 v1(110.3,51.9)
  other v1: 126,43.5 126.7,43.5 127.4,43.5 126,44.2 126.7,44.2 127.4,44.2 126,44.9 126.7,44.9 127.4,44.9 126,45.6 126.7,45.6 127.4,45.6 126,46.3 126.7,46.3 127.4,46.3 110.3,51.2 111,51.2 111.7,51.2 112.4,51.2 113.1,51.2 113.8,51.2 111,51.9 111.7,51.9 112.4,51.9 113.1,51.9 113.8,51.9
  other v3: 51.8,-29 51.8,-28 52.8,-28 52.8,-27 53.8,-27 52.8,-26 53.8,-26 54.8,-26 52.8,-25 53.8,-25 54.8,-25 55.8,-25
VSYS: R29.2 R354.2 U5.AL6 U5.AL7 U5.AL8 | length 24.3
  1-TOP w0.2: U5.AL6@17.78,-11.43 v1(18.415,-12.065) ; U5.AL7@17.78,-10.16 v1(18.415,-10.795) ; U5.AL8@17.78,-8.89 v1(18.415,-9.525) ; v3(40.9,-12.5) 40,-13.4 40,-22.5 44.5,-27 R354.2@44.5,-28.52
  1-TOP w0.8: v3(43.3,-12.5) R29.2@44.2,-12.5
  1-TOP w1: v3(40.9,-12.5) v3(41.7,-12.5) v3(42.5,-12.5) v3(43.3,-12.5)
VSYS2: J5.1 R30.2 U5.AJ2 U5.AJ3 U5.AJ4 U5.AK2 U5.AK3 U5.AK4 | length 132
  1-TOP w0.2: U5.AJ2@15.24,-16.51 v1(15.875,-17.145) ; U5.AJ3@15.24,-15.24 v1(15.875,-15.875) ; U5.AJ4@15.24,-13.97 v1(15.875,-14.605) ; U5.AK2@16.51,-16.51 v1(17.145,-17.145) ; U5.AK3@16.51,-15.24 v1(17.145,-15.875) ; U5.AK4@16.51,-13.97 v1(17.145,-14.605)
  1-TOP w0.8: v3(43.3,-14.5) R30.2@44.2,-14.5
  1-TOP w1: v3(40.9,-14.5) v3(41.7,-14.5) v3(42.5,-14.5) v3(43.3,-14.5)
  8-BOTTOM w1.5: v3(40.9,-14.5) v3(41.7,-14.5) v3(42.5,-14.5) v3(43.3,-14.5) 45,-12.8 45,14 74,43 78.5,43 94,58.5 114.5,58.5 116.27,60.27 J5.1@116.27,61.5
WL_DEV_WAKE: J49.15 U5.F24 | length 65.1
  1-TOP w0.2: U5.F24@-13.97,11.43 v1(-13.335,10.795)
  3-INTOP w0.15: J49.15@-65.73,-6.65 -64,-4.92 -64,-0.6 -58.9,4.5 -21.75,4.5 -21.33,4.92 -15.91,4.92 -15.23,5.6 -15.23,5.8 -14.73,6.3 -14.47,6.3 -13.97,6.8 -13.97,10.16 v1(-13.335,10.795)
WL_HOST_WAKE: J49.13 U5.G18 | length 62.5
  1-TOP w0.2: v1(-13.335,4.445) U5.G18@-12.7,3.81
  3-INTOP w0.15: J49.13@-65.73,-9.19 -63.5,-6.96 -63.5,-0.8 -59.2,3.5 -22,3.5 -21.85,3.65 -14.13,3.65 v1(-13.335,4.445)
WLAN_SD1_CLK: J49.17 R40.2 | length 5.5
  1-TOP w0.2: J49.17@-65.73,-4.11 -64.51,-4.11 -63.9,-3.5 R40.2@-60.48,-3.5
WLAN_SD1_CMD: J49.19 R41.2 | length 5.4
  1-TOP w0.2: J49.19@-65.73,-1.57 -64.43,-1.57 -64,-2 R41.2@-60.48,-2
WLAN_SD1_D0: J49.2 R43.2 | length 9
  1-TOP w0.2: J49.2@-68.27,-24.43 -67,-23.16 -65.16,-23.16 -63.5,-21.5 R43.2@-60.48,-21.5
WLAN_SD1_D1: J49.4 R44.2 | length 9.2
  1-TOP w0.2: J49.4@-68.27,-21.89 -67,-20.62 -65.22,-20.62 -63.1,-18.5 R44.2@-60.48,-18.5
WLAN_SD1_D2: J49.6 R45.2 | length 9.4
  1-TOP w0.2: J49.6@-68.27,-19.35 -67,-18.08 -65.18,-18.08 -62.6,-15.5 R45.2@-60.48,-15.5
WLAN_SD1_D3: J49.8 R47.2 | length 9.6
  1-TOP w0.2: J49.8@-68.27,-16.81 -67,-15.54 -65.24,-15.54 -62.2,-12.5 R47.2@-60.48,-12.5
WLAN_SD1_D4: J49.10 R48.2 | length 9.8
  1-TOP w0.2: J49.10@-68.27,-14.27 -67,-13 -65.3,-13 -61.8,-9.5 R48.2@-60.48,-9.5
WLAN_SD1_D5: J49.12 R49.2 | length 9.3
  1-TOP w0.2: J49.12@-68.27,-11.73 -67,-10.46 -64.96,-10.46 -62.5,-8 R49.2@-60.48,-8
WLAN_SD1_D6: J49.14 R50.2 | length 8.9
  1-TOP w0.2: J49.14@-68.27,-9.19 -67,-7.92 -64.92,-7.92 -63.5,-6.5 R50.2@-60.48,-6.5
WLAN_SD1_D7: J49.16 R52.2 | length 8.5
  1-TOP w0.2: J49.16@-68.27,-6.65 -67,-5.38 -64.38,-5.38 -64,-5 R52.2@-60.48,-5
WOL_INT: R181.2 U5.Y1 U15.40 | length 79.8
  1-TOP w0.15: U15.40@-52,-30.05 -52,-29.5
  1-TOP w0.2: -52,-29.5 -52,-26.7 -51.2,-25.9 R181.2@-51.2,-25.48 -50.78,-25.48 -50.6,-25.3 -50.6,-24.1 -50.4,-23.9 -48.7,-23.9 -47.8,-23 -47.105,-23 v1@-34.903,-10.797 ; U5.Y1@3.81,-17.78 v1(7.371,-21.477)
  3-INTOP w0.15: v1(-34.9,-10.8) -33.2,-12.5 -25.2,-12.5 -16.223,-21.477 v1(7.371,-21.477)
X_N: R64.2 U5.G3 | length 57.3
  1-TOP w0.192: R64.2@18.9,-40.3 18.546,-39.946 18.483,-39.946 18.371,-39.834 18.371,-21.629 18.529,-21.471 18.663,-21.471 18.817,-21.625 v1(18.9,-21.625)
  1-TOP w0.2: v1(-13.335,-14.605) U5.G3@-12.7,-15.24
  8-BOTTOM w0.192: v1(-13.335,-14.605) -12.871,-15.069 -12.871,-15.387 -13.042,-15.558 -13.042,-17.542 -11.242,-19.342 14.658,-19.342 16.787,-21.471 18.663,-21.471 18.817,-21.625 v1(18.9,-21.625)
X_P: R63.2 U5.G4 | length 57.3
  1-TOP w0.192: R63.2@17.5,-40.3 17.854,-39.946 17.917,-39.946 18.029,-39.834 18.029,-21.487 18.387,-21.129 18.663,-21.129 18.817,-20.975 v1(18.9,-20.975)
  1-TOP w0.2: U5.G4@-12.7,-13.97 v1(-12.065,-14.605)
  8-BOTTOM w0.192: v1(-12.065,-14.605) -12.529,-15.069 -12.529,-15.529 -12.7,-15.7 -12.7,-17.4 -11.1,-19 14.8,-19 16.929,-21.129 18.663,-21.129 18.817,-20.975 v1(18.9,-20.975)
XBEE1_ON/SLEEP_N: J40.8 U5.AL24 | length 152.8
  1-TOP w0.2: U5.AL24@17.78,11.43 v1(18.415,12.065) ; J40.8@123,-26.925 123,-18 126.3,-14.7 v1(126.3,-0.9)
  3-INTOP w0.15: v1(18.415,12.065) 20.12,12.065 21.185,11 27.1,11 30.1,14 39.8,14 40.8,15 59.5,15 60,14.5 74.6,14.5 77.1,17 84.6,17 88.1,20.5 109.9,20.5 120,10.4 120,5.4 v1(126.3,-0.9)
XBEE1_RESET_N: J39.5 U5.AL25 | length 130.8
  1-TOP w0.2: U5.AL25@17.78,12.7 v1(18.415,13.335) ; J39.5@129,-2.075 v1(129,-0.5)
  3-INTOP w0.15: v1(18.415,13.335) 20.95,13.335 21.785,12.5 26.5,12.5 30,16 39,16 40,17 60.3,17 60.8,16.5 73.8,16.5 76.3,19 83.8,19 87.8,23 108.1,23 120.5,10.6 120.5,5.6 126.6,-0.5 v1(129,-0.5)
XBEE1_SLEEP_RQ: J39.9 U5.AM26 | length 116.2
  1-TOP w0.2: U5.AM26@19.05,13.97 20,14.92 20,15.707 23.293,19 30,19 v1(38.5,10.5) ; J39.9@121,-2.075 v1(121,3)
  3-INTOP w0.15: v1(38.5,10.5) 42.5,6.5 81.693,6.5 83.693,4.5 119.5,4.5 v1(121,3)
XBEE1_UART_CTS: J45.10 R336.2 U5.AN23 | length 138.1
  1-TOP w0.2: U5.AN23@20.32,10.16 v1(36.74,10.16) ; v1(85.65,3) 85.65,10 J45.10@86.92,11.27 ; R336.2@121,-20.02 121,-19.3 125.8,-14.5 v1(125.8,-4.1)
  3-INTOP w0.15: v1(36.74,10.16) 41.9,5 81.1,5 81.5,4.6 83.1,3 98.35,3 118.7,3 v1(125.8,-4.1)
XBEE1_UART_RTS: J45.8 R307.2 R335.2 U5.AL27 | length 149.6
  1-TOP w0.2: U5.AL27@17.78,15.24 22.54,20 31.5,20 v1(41,10.5) ; R335.2@129.98,-21.5 R307.2@129.98,-20.02 ; R307.2@129.98,-20 R307.2@129.98,-20.02 ; v1(130.6,-20.02) R307.2@129.98,-20.02
  3-INTOP w0.15: v1(41,10.5) 44.5,7 82.5,7 85.5,10 88.19,10 J45.8@89.46,11.27 90.7,10.03 90.7,6.3 92,5 119.7,5 133.2,-8.5 133.2,-17.42 v1(130.6,-20.02)
XBEE1_UART_RX: J45.4 R333.1 U5.AN22 | length 128.5
  1-TOP w0.2: U5.AN22@20.32,8.89 v1(39.41,8.89) ; v1(93.27,4) 93.27,10 J45.4@94.54,11.27 ; v1(132.7,-9.6) R333.1@132.7,-8.98
  3-INTOP w0.15: v1(39.41,8.89) 42.3,6 81.5,6 83.5,4 119.1,4 v1(132.7,-9.6)
XBEE1_UART_TX: J45.2 R334.1 U5.AN21 | length 127.5
  1-TOP w0.2: U5.AN21@20.32,7.62 22.08,7.62 22.7,7 v1(40.6,7) ; v1(95.81,3.5) 95.81,10 J45.2@97.08,11.27 ; v1(131.5,-9.6) R334.1@131.5,-8.98
  3-INTOP w0.15: v1(40.6,7) 42.1,5.5 81.3,5.5 83.3,3.5 v1(95.81,3.5) 118.907,3.5 131.5,-9.093 v1(131.5,-9.6)
XBEE1_USB_D_N: J39.8 L26.2 U25.4 | length 18
  1-TOP w0.168: U25.4@118.4,-14.95 120.2,-14.95 120.4,-14.75 L26.2@120.4,-14.1 ; L26.2@120.4,-14.15 120.4,-13.9 120.284,-13.784 120.257,-13.784 120.159,-13.686 120.159,-5.541 122.6,-3.1 123.511,-3.1 123.711,-3.3 123.711,-3.439 123,-4.15 J39.8@123,-4.925
XBEE1_USB_D_P: J39.7 L26.3 U25.5 | length 17.4
  1-TOP w0.168: U25.5@118.4,-14 L26.3@119.6,-14 ; L26.3@119.6,-14.15 L26.3@119.6,-14 ; J39.7@125,-2.075 125,-2.85 124.684,-3.166 124.027,-3.166 123.643,-2.782 122.468,-2.782 119.841,-5.409 119.841,-13.686 119.743,-13.784 119.716,-13.784 119.6,-13.9 L26.3@119.6,-14
XBEE1_VCC: C174.2 C175.2 J39.1 L38.2 L39.2 | length 8.9
  1-TOP w0.5: L39.2@137,-11 C174.2@137,-9 J39.1@137,-2.075
XBEE2_ON/SLEEP_N: J42.8 U5.AG12 | length 116
  1-TOP w0.2: U5.AG12@12.7,-3.81 v1(13.335,-4.445) ; v1(123,-2) J42.8@123,2.075
  3-INTOP w0.15: v1(13.335,-4.445) 13.81,-4.92 20.08,-4.92 21.5,-3.5 121.5,-3.5 v1(123,-2)
XBEE2_RESET_N: J41.5 U5.AG11 | length 143.3
  1-TOP w0.2: U5.AG11@12.7,-5.08 v1(13.335,-5.715) ; v1(118,-5.5) 118,9.5 129,20.5 J41.5@129,26.925
  3-INTOP w0.15: v1(13.335,-5.715) 14.13,-6.51 21.59,-6.51 22.6,-5.5 v1(118,-5.5)
XBEE2_SLEEP_RQ: J41.9 U5.AG9 | length 142.8
  1-TOP w0.2: U5.AG9@12.7,-7.62 v1(13.335,-8.255) ; v1(117,-7) 117.5,-6.5 117.5,9.7 121,13.2 J41.9@121,26.925
  3-INTOP w0.15: v1(13.335,-8.255) 13.97,-8.89 22.01,-8.89 23.4,-7.5 50.5,-7.5 52.5,-9.5 88,-9.5 90.5,-7 v1(117,-7)
XBEE2_UART_CTS: J42.5 R312.2 U5.E22 | length 178.3
  1-TOP w0.2: v1(-15.875,9.525) U5.E22@-15.24,8.89 ; v1(128.4,7.5) R312.2@129,7.5 ; J42.5@129,4.925 R312.2@129,7.5 ; R312.2@129.02,7.5 R312.2@129,7.5
  3-INTOP w0.15: v1@-0.8,33.5 49.5,33.5 51.5,31.5 90.4,31.5 91,32.1 102,32.1 104.725,29.375 104.725,27.775 125,7.5 v1(128.4,7.5)
  6-INBOT w0.15: v1(-15.875,9.525) -17.125,9.525 -17.94,10.34 -17.94,15.752 -17.192,16.5 -17,16.5 -15.24,18.26 -15.24,19.06 v1(-0.8,33.5)
XBEE2_UART_RTS: J42.9 U5.E19 | length 176
  1-TOP w0.2: v1(-15.875,5.715) U5.E19@-15.24,5.08 ; J42.9@121,4.925 v1(121,6.5)
  3-INTOP w0.15: v1(-2,33) 49.3,33 51.3,31 90.6,31 91.2,31.6 101.3,31.6 103.4,29.5 103.4,28.4 121,10.8 v1(121,6.5)
  6-INBOT w0.15: v1(-15.875,5.715) -16.307,5.715 -17,6.408 -17,8.7 -18.89,10.59 -18.89,15.61 -17.78,16.72 -17.78,17.22 -17.22,17.78 -17.02,17.78 -16.51,18.29 -16.51,18.49 v1(-2,33)
XBEE2_UART_RX: J41.2 R154.2 | length 149.5
  1-TOP w0.2: R154.2@-4.4,37.5 v1(-3.6,37.5) ; J41.2@135,24.075 v1(135,25.6)
  3-INTOP w0.15: v1(-3.6,37.5) 86.5,37.5 88.5,39.5 124.5,39.5 130.5,33.5 130.5,30.1 v1(135,25.6)
XBEE2_UART_TX: J41.3 R152.2 | length 146.9
  1-TOP w0.2: R152.2@-4.4,39 v1(-3.6,39) ; J41.3@133,26.925 v1(133,28.45)
  3-INTOP w0.15: v1(-3.6,39) 3,39 4,38 7.2,38 86.3,38 88.3,40 124.7,40 131,33.7 131,30.45 v1(133,28.45)
XBEE2_VCC: C176.2 C177.2 J41.1 L40.2 L41.2 | length 8.9
  1-TOP w0.5: L41.2@137,18 C176.2@137,20 J41.1@137,26.925
Y_N: R66.2 U5.G9 | length 103.1
  1-TOP w0.192: R66.2@69.6,-23.6 69.621,-23.6 69.975,-23.954 v1(69.975,-24.4)
  1-TOP w0.2: v1(-13.335,-6.985) U5.G9@-12.7,-7.62
  8-BOTTOM w0.192: v1(-13.335,-6.985) -12.986,-6.985 -12.871,-7.1 -12.871,-7.787 -15.342,-10.258 -15.342,-18.542 -10.109,-23.774 69.974,-23.774 70.129,-23.929 70.129,-24.163 69.975,-24.317 v1(69.975,-24.4)
Y_P: R65.2 U5.G10 | length 103.1
  1-TOP w0.192: v1(70.625,-24.4) 70.625,-23.954 70.979,-23.6 R65.2@71,-23.6
  1-TOP w0.2: U5.G10@-12.7,-6.35 v1(-12.065,-6.985)
  8-BOTTOM w0.192: v1(-12.065,-6.985) -12.414,-6.985 -12.529,-7.1 -12.529,-7.929 -15,-10.4 -15,-18.4 -9.968,-23.432 70.116,-23.432 70.471,-23.787 70.471,-24.163 70.625,-24.317 v1(70.625,-24.4)
Z_N: R68.2 U5.G6 | length 94.3
  1-TOP w0.192: R68.2@66.4,-21.6 66.421,-21.6 66.775,-21.954 v1(66.775,-22.4)
  1-TOP w0.2: v1(-13.335,-10.795) U5.G6@-12.7,-11.43
  8-BOTTOM w0.192: v1(-13.335,-10.795) -12.986,-10.795 -12.871,-10.91 -12.871,-11.181 -14.242,-12.552 -14.242,-18.042 -9.436,-22.847 62.9,-22.848 63.973,-21.774 66.774,-21.774 66.929,-21.929 66.929,-22.163 66.775,-22.317 v1(66.775,-22.4)
Z_P: R67.2 U5.G7 | length 94.3
  1-TOP w0.192: v1(67.425,-22.4) 67.425,-21.954 67.779,-21.6 R67.2@67.8,-21.6
  1-TOP w0.2: U5.G7@-12.7,-10.16 v1(-12.065,-10.795)
  8-BOTTOM w0.192: v1(-12.065,-10.795) -12.414,-10.795 -12.529,-10.91 -12.529,-11.323 -13.9,-12.694 -13.9,-17.9 -9.295,-22.505 62.758,-22.505 63.832,-21.432 66.916,-21.432 67.271,-21.787 67.271,-22.163 67.425,-22.317 v1(67.425,-22.4)
pads on no net: D8.X FIDUCIAL1.1 FIDUCIAL2.1 FIDUCIAL3.1 FIDUCIAL4.1 FIDUCIAL5.1 FIDUCIAL6.1 H1.1 H2.1 H3.1 H4.1 J1.3 J1.4 J12.8 J12.9 J16.4 J16.10 J16.11 J19.3 J19.5 J19.7 J19.17 J19.19 J19.42 J19.44 J19.45 J19.46 J19.47 J19.49 J19.51 J19.H1 J19.H2 J19.MT1 J19.MT2 J20.7 J21.4 J21.8 J21.9 J21.10 J22.6 J22.7 J22.8 J27.MNT1 J27.MNT2 J29.4 J31.14 J31.H1 J31.H2 J32.MT1 J32.MT21 J34.10 J34.11 J35.10 J35.11 J40.1 J40.2 J40.3 J40.4 J40.6 J41.7 J41.8 J42.1 J42.2 J42.3 J42.4 J42.6 SWD.6 SWD.7 SWD.8 SWD.9 SWD.MT1 SWD.MT2 SWD.MT3 U1.11 U5.A26 U5.AB1 U5.AB29 U5.AC1 U5.AC29 U5.AD1 U5.AE1 U5.AG24 U5.AG25 U5.AH9 U5.AH11 U5.AH15 U5.AH16 U5.AH29 U5.AJ8 U5.AJ13 U5.AJ15 U5.AJ16 U5.AJ18 U5.AJ19 U5.AJ29 U5.AK15 U5.AK16 U5.AK18 U5.AK19 U5.AK29 U5.AL28 U5.AM22 U5.B7 U5.B9 U5.B10 U5.B12 U5.B13 U5.B23 U5.C3 U5.C21 U5.C22 U5.C23 U5.C27 U5.D1 U5.D20 U5.D21 U5.D22 U5.D23 U5.F2 U5.F4 U5.F5 U5.F6 U5.F7 U5.F8 U5.F9 U5.F10 U5.F26 U5.F27 U5.G20 U5.G21 U5.G23 U5.G24 U5.J29 U5.K29 U5.L29 U5.MH1 U5.MH2 U5.MH3 U5.MH4 U5.MH5 U5.MH6 U7.1 U7.9 U7.11 U9.1 U9.2 U9.13 U9.15 U9.16 U9.17 U9.19 U9.20 U9.21 U9.22 U9.29 U9.30 U9.32 U9.33 U9.35 U9.36 U9.37 U9.38 U9.41 U9.48 U10.3 U15.22 U15.25 U15.26 U15.42 U15.43 U15.45 U15.46 U17.7 U17.24 U18.1 U18.2 U18.7 U18.16 U18.17 U18.22 U18.23 U18.24 U19.15 U19.16 U19.19 U19.20 U19.37 U19.38 U19.39 U19.40 U19.43 U19.44 U19.45 U19.46 U19.47 U19.48 U20.16 U21.1 U21.4 U21.5 U21.6 U21.7 U21.8 U21.9 U21.10 U21.11 U21.12 U21.13 U21.34 U21.50 U21.51 U21.53 U21.54 U21.56 U21.57 U21.59 U21.60 U21.61 U21.62 U22.6 U24.18 U24.19 U24.20 U24.21 U25.6 U27.3 U27.5 U29.11 U29.12 U29.13 U29.14 U29.28 U29.29 U29.40 U29.41 U29.46 U36.3 U36.5
copper on no net: | length 0.9
  1-TOP w0.2: 12.7,11.43 v1(13.335,12.065)
  other v3: 130,46.5 130,47.5

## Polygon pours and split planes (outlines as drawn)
GND on 1-TOP "GND_PLANE" (solid, remove dead copper, pour order 62): -70,-65 140,-65 140,65 -70,65
NetC187_1 on 1-TOP "NetC187_1" (solid, remove dead copper, pour order 42): -32.4,-44.6 -32.1,-44.9 -27.9,-44.9 -27.3,-44.3 -27.3,-38.5 -27.5,-38.3 -30.099,-38.299 -30.3,-38.5 -30.3,-41.8 -30.5,-42 -31.4,-42 -32.4,-43
NetC191_1 on 1-TOP "NetC191_1" (solid, remove dead copper, pour order 40): -38.4,-44.6 -38.1,-44.9 -33.9,-44.9 -33.3,-44.3 -33.3,-38.5 -33.5,-38.3 -36.099,-38.299 -36.3,-38.5 -36.3,-41.8 -36.5,-42 -37.4,-42 -38.4,-43
VIN_PROT on 1-TOP "VIN_PROT" (solid, remove dead copper, pour order 4): 125.5,41.5 126.5,40.5 128.5,40.5 129,41 129,47.3 127.8,47.3 126.3,47.3 125.5,46.5
3V3_SOM_EXT on 1-TOP "3V3_SOM_EXT" (solid, remove dead copper, pour order 22): -54.3,12.3 -53,13.6 -53,16.6 -53.2,16.8 -55.9,16.8 -56.1,16.6 -56.1,12.5 -55.9,12.3
3V3_SOM_EXT on 1-TOP "3V3_SOM_EXT" (solid, remove dead copper, pour order 14): -51.7,-10.3 -53,-11.6 -53,-14.6 -52.8,-14.8 -50.1,-14.8 -49.9,-14.6 -49.9,-10.5 -50.1,-10.3
3V3_SOM_EXT on 1-TOP "3V3_SOM_EXT" (solid, remove dead copper, pour order 8): 95.8,-37.2 97.1,-38.5 100.1,-38.5 100.3,-38.3 100.3,-35.6 100.1,-35.4 96,-35.4 95.8,-35.6
3V3_BOARD on 1-TOP "3V3_BOARD" (solid, remove dead copper, pour order 24): 110.8,40.7 111,40.5 117.8,40.5 119.2,41.9 119.2,44.3 119,44.5 111,44.5 110.8,44.3
GND on 1-TOP "GND" (solid, remove dead copper, pour order 52): 122,57 122.5,56.5 127.5,56.5 128,57 128,60 127.5,60.5 122.5,60.5 122,60
VIN_PROT on 1-TOP "3V3" (solid, remove dead copper, pour order 44): 50.4,-24.6 50.1,-24.9 50.1,-29.1 50.4,-29.4 51.9,-29.4 56.2,-25.1 56.2,-24.9 55.9,-24.6
1V8_SOM_EXT on 1-TOP "3V3_SOM_EXT" (solid, remove dead copper, pour order 38): -38.4,-45.4 -38.1,-45.1 -33.9,-45.1 -33.6,-45.4 -33.6,-47.9 -33.9,-48.2 -38.1,-48.2 -38.4,-47.9
3V3_SOM_EXT on 1-TOP "3V3_SOM_EXT" (solid, remove dead copper, pour order 36): -32.4,-45.4 -32.1,-45.1 -27.9,-45.1 -27.6,-45.4 -27.6,-47.9 -27.9,-48.2 -32.1,-48.2 -32.4,-47.9
NetFIL1_1 on 1-TOP "VIN_PROT" (solid, remove dead copper, pour order 32): 121.5,51 122.5,50 131.5,50 135.4,46.1 138.6,46.1 139,46.5 139,54.5 138,55.5 122.5,55.5 121.5,54.5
